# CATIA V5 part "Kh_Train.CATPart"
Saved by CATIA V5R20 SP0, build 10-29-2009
Part number: Train
Bounding box of the stored display mesh (mm): x 20 to 150, y 0 to 197.1, z 0 to 93
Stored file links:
  G:\Khaled_CFAO_2011\SIL\SIL_GR1\tmerino\Khaled\CAD_Thinkmotion\Kh_Train.CATPart
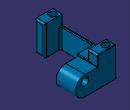
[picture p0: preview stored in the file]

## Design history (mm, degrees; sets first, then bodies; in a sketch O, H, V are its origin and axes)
Parameters
  `Longueur côté` = 80 mm
  `Largeur côté` = 30 mm
  Extrusion = 80 mm
Body1 (main body)
  Sketch1 on yz-plane, origin (0, 0, 0), H (0, 1, 0), V (0, 0, 1)
    line L1 (0, 0) -> (197.1, 0)
    line L2 (0, 0) -> (0, 0)
    line L3 (0, 0) -> (0, 93)
    line L4 (0, 93) -> (30, 93)
    line L5 (30, 93) -> (30, 63)
    line L6 (197.1, 0) -> (197.1, 93)
    line L7 (197.1, 93) -> (167.1, 93)
    line L8 (167.1, 93) -> (167.1, 63)
    line L9 (30, 63) -> (167.1, 63)
    length L1 = 197.1
    length L4 = 30 {= `Largeur côté`}
    length L7 = 30 {= `Largeur côté`}
    distance L7 L1 = 93
    distance L4 L1 = 93
    length L5 = 30
    horizontal: L1 H, L2 H, L4 H, L7 H, L9 H
    vertical: L3 V, L5 V, L6 V, L8 V
  Pad1: profile Sketch1, direction (1, 0, 0), length 80 {= Extrusion}
  Sketch2 on face of Pad1 from Sketch1.L7, origin (0, 0, 93), H (1, 0, 0), V (0, 1, 0)
    circle A1 centre (40, 182.1) radius 11
    point P1 (40, 182.1)
    circle A2 centre (40, 15) radius 11
    point P2 (40, 15)
    reference projected line E1 (80, 30) -> (80, 0) from edge [face of Pad1 from Sketch1.L4 | end face of Pad1]
    reference projected line E2 (0, 140) -> (0, 110) from edge [start face of Pad1 | face of Pad1 from Sketch1.L7]
    reference projected line E3 (0, 0) -> (80, 0) from edge [face of Pad1 from Sketch1.L3 | face of Pad1 from Sketch1.L4]
    reference projected line E4 (0, 197.1) -> (80, 197.1) from edge [face of Pad1 from Sketch1.L7 | face of Pad1 from Sketch1.L6]
    radius A2 = 11
    radius A1 = 11
    distance P2 E1 = 40 {= Extrusion /2}
    distance P1 E2 = 40 {= Extrusion /2}
    distance P2 E3 = 15 {= `Largeur côté` /2}
    distance E4 P1 = 15 {= `Largeur côté` /2}
  Pocket1: profile Sketch2, direction (0, 0, -1), through (limit type 3)
  Sketch3 on face of Pad1 from Sketch1.L6, origin (0, 197.1, 0), H (-1, 0, 0), V (0, 0, 1)
    line L1 (-80, 60) -> (-120, 60)
    line L2 (-80, 0) -> (-120, 0)
    point P3 (-80, 0)
    arc A1 centre (-120, 30) radius 30 from (-120, 60) to (-120, 0) ccw
    line L3 (-80, 60) -> (-80, 0)
    reference projected line E1 (-80, 0) -> (-80, 93) from edge [face of Pad1 from Sketch1.L6 | end face of Pad1]
    length L1 = 40
    distance E1 L3 = 0
    length L2 = 40
    horizontal: L1 H, L2 H
    coincidence: P3 H
    tangency: A1 L1
    vertical: L3 V
  Pad2: profile Sketch3, direction (0, -1, 0), length 60.648
  Sketch4 on face of Pad2, origin (0, 197.1, 0), H (-1, 0, 0), V (0, 0, 1)
    circle A1 centre (-120, 41) radius 11
    point P1 (-120, 41)
    reference projected line E1 (0, 93) -> (-80, 93) from edge [face of Pad1 from Sketch1.L7 | face of Pad1 from Sketch1.L6]
    reference projected line E2 (-80, 0) -> (-80, 93) from edge [face of Pad2 | end face of Pad1]
    radius A1 = 11
    distance E1 P1 = 52
    distance P1 E2 = 40
  Pocket2: profile Sketch4, direction (0, -1, 0), through (limit type 3)
  Sketch5 on face of Pad2, origin (0, 0, 0), H (1, 0, 0), V (0, -1, 0)
    line L1 (30, -30) -> (160, -30)
    line L2 (160, -30) -> (160, -130)
    line L3 (160, -130) -> (30, -130)
    line L4 (30, -130) -> (30, -30)
    reference projected line E1 (0, 0) -> (80, 0) from edge [face of Pad1 from Sketch1.L1 | face of Pad1 from Sketch1.L3]
    distance E1 L3 = 130
    horizontal: L1 H, L3 H
    vertical: L2 V, L4 V
  Pocket3: profile Sketch5, direction (0, 0, 1), through (limit type 3)
  Fillet1: radius 2, on edge [end face of Pad2 | end face of Pad1]
  Fillet2: radius 3, on edge [end face of Pad1 | face of Pocket3 from Sketch5.L3]
  Fillet3: radius 5, on edge [face of Pocket3 from Sketch5.L3 | face of Pocket3 from Sketch5.L4]
  Fillet4: radius 5, on edge [face of Pocket3 from Sketch5.L4 | face of Pocket3]
  Sketch6 on face of Pad2, origin (0, 197.1, 0), H (-1, 0, 0), V (0, 0, 1)
    line L1 (-20, 120) -> (30, 120)
    line L2 (30, 120) -> (30, -20)
    line L3 (30, -20) -> (-20, -20)
    line L4 (-20, -20) -> (-20, 120)
    horizontal: L1 H, L3 H
    vertical: L2 V, L4 V
  Pocket4: profile Sketch6, direction (0, -1, 0), through (limit type 3)
  Fillet5: radius 5, on end face of Pad1
  Fillet6: radius 5, on face of Pocket4 from Sketch6.L4
  Fillet7: radius 5, on edge [face of Pad1 from Sketch1.L7 | end face of Pad1]
  Fillet8: radius 1, on edge [face of Pad2 | end face of Pad1]; edge [face of Pad2 from Sketch3.L1 | end face of Pad1]
  Fillet9: radius 2, on edge [face of Pad1 from Sketch1.L9 | end face of Pad1]
Relations
  Pad1.FirstLimit.Length = Extrusion (deactivated)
